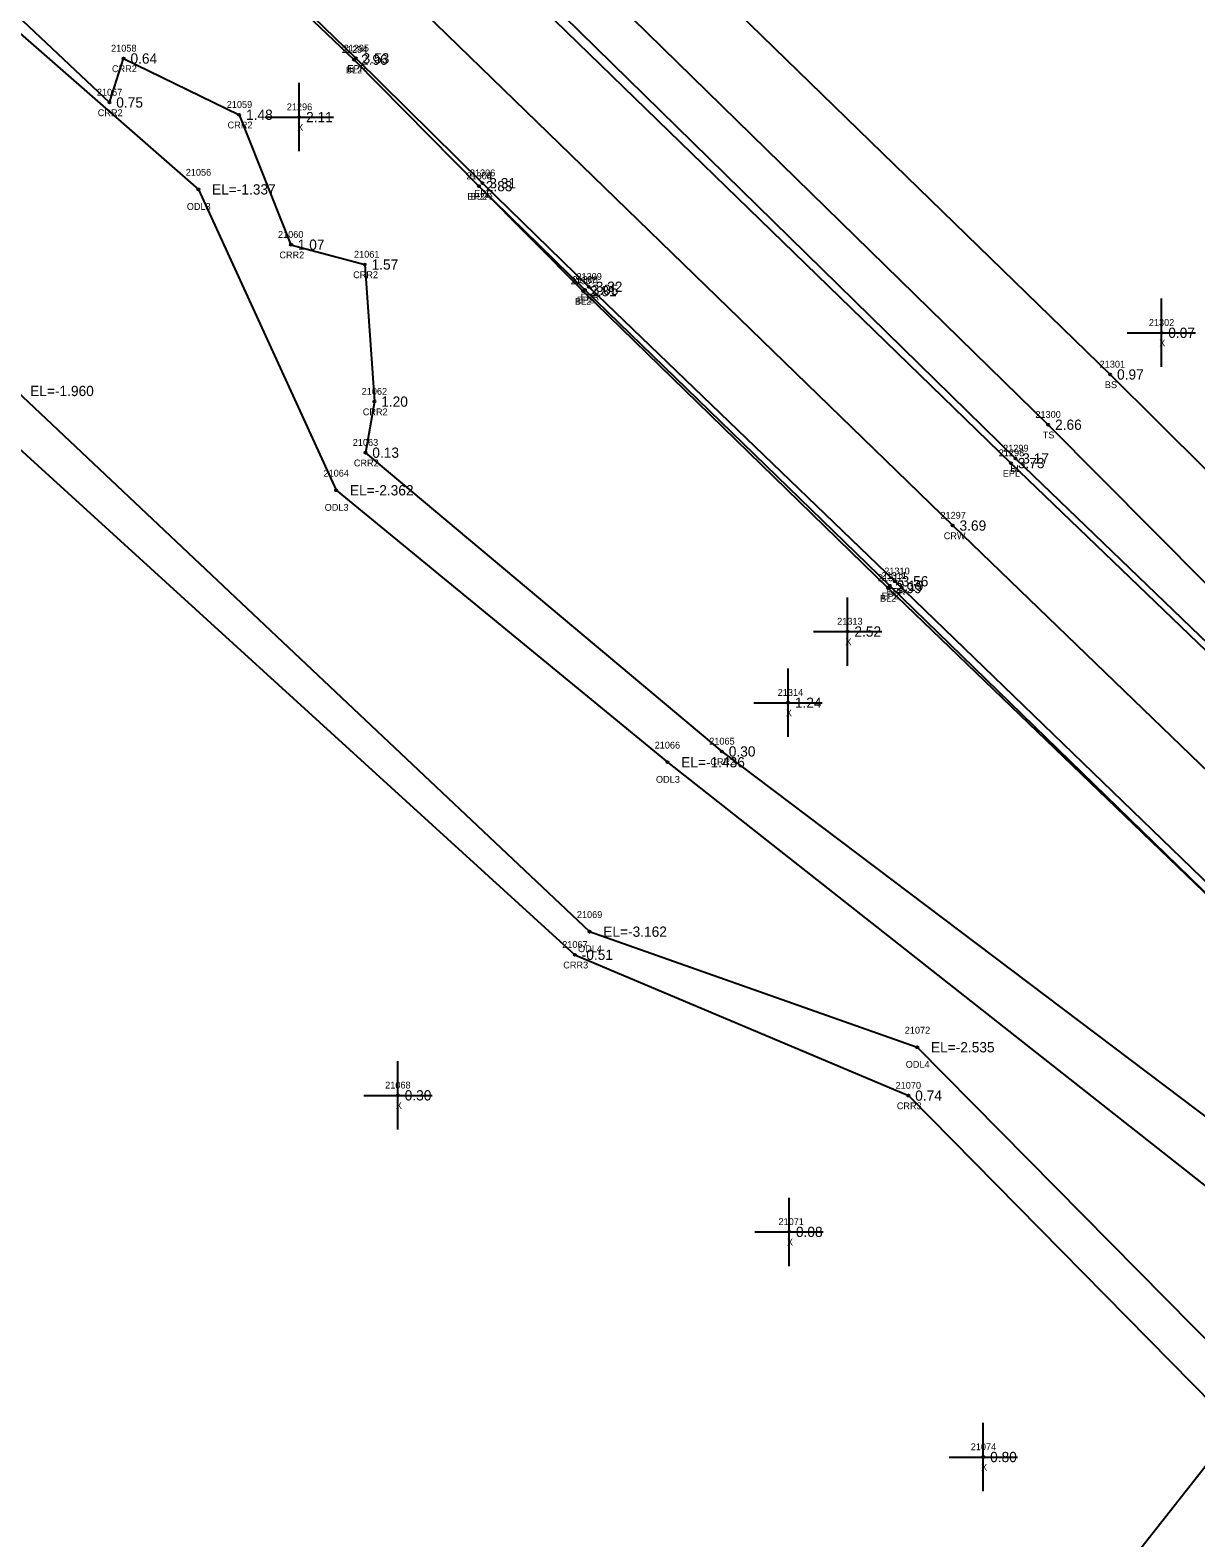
# Model space of a CAD drawing. Extents: x 2608745 to 2610333, y 641917 to 643463.
# Drawn here: x 2609715.3 to 2609885.8, y 642225.6 to 642446.2 of the extents above; entities that cross this region are included whole.
import ezdxf

# ---------------------------------------------------------------- set-up
doc = ezdxf.new("R2010")
doc.units = 0
for name, color, linetype in [('RD_DTM_BkLn1', 7, 'Continuous'), ('RD_DTM_BkLn2', 7, 'Continuous'), ('RD_DTM_BkLn_txCode', 7, 'Continuous'), ('RD_EX_H2O', 7, 'Continuous'), ('RD_EX_H2O_txCode', 7, 'Continuous'), ('RD_EX_Misc', 7, 'Continuous'), ('RD_EX_Misc_txCode', 7, 'Continuous'), ('RD_EX_Road', 7, 'Continuous'), ('RD_EX_Road_txCode', 7, 'Continuous'), ('RD_EX_TX_H2O_ELEV', 7, 'Continuous'), ('RD_EX_TX_Misc_ELEV', 7, 'Continuous'), ('RD_EX_TX_Road_ELEV', 7, 'Continuous'), ('RD_HC_Survey_ELEV', 7, 'Continuous'), ('RD_HC_Survey_txCode', 7, 'Continuous'), ('RD_SMD_Locator', 7, 'Continuous')]:
    doc.layers.add(name, color=color, linetype=linetype)

msp = doc.modelspace()

# ---------------------------------------------------------------- linework, layer by layer
at = {"layer": 'RD_DTM_BkLn1'}
for points in [[(2609568.4, 642647.43), (2609618.95, 642597.92), (2609693.89, 642525.38), (2609771.33, 642450.27), (2609850.26, 642373.69), (2609929.54, 642297.24), (2610000.01, 642230.49), (2610078.71, 642154.75), (2610156.09, 642080.44), (2610235.53, 642002.94), (2610263.59, 641975.77)], [(2609627.58, 642607.09), (2609630.23, 642605.37), (2609646.31, 642589.45), (2609703.16, 642535.02), (2609781.51, 642459.84), (2609859.44, 642383.51), (2609938.95, 642307.03), (2610008.76, 642239.49), (2610086.74, 642162.99), (2610105.31, 642145.89), (2610105.31, 642145.89), (2610140.26, 642113.1), (2610153.89, 642100.28), (2610164.72, 642089.82), (2610189.2, 642065.46)], [(2609638.64, 642561.68), (2609646.49, 642552.99), (2609655.41, 642544.68), (2609682.3, 642518.46), (2609696.97, 642504.35), (2609720.79, 642481.57), (2609738.97, 642465.02), (2609753.66, 642450.39), (2609762.69, 642441.83), (2609780.95, 642423.34), (2609796.2, 642407.99), (2609840.83, 642364.55), (2609897.27, 642310.29), (2609920.64, 642289.07), (2609961.88, 642250.25), (2609968.31, 642243.41), (2609978.92, 642233.98)]]:
    msp.add_lwpolyline(points, dxfattribs=at)
at = {"layer": 'RD_DTM_BkLn2'}
for points in [[(2609582.66, 642657.54), (2609585.75, 642657.34), (2609622.53, 642623.2), (2609632.13, 642611.9), (2609647.4, 642591.36), (2609682.93, 642558.52), (2609706.14, 642537.77), (2609755.54, 642496.98), (2609786.05, 642464.88), (2609864.24, 642388.44), (2609941.53, 642310.67), (2610012.94, 642244.46), (2610082.83, 642179.18), (2610093.52, 642170.29)], [(2609755.54, 642496.98), (2609777.06, 642487.55), (2609794.23, 642472.67), (2609873.31, 642395.79), (2609950.73, 642318.92), (2610015.83, 642247.73), (2610085.46, 642180.03), (2610093.52, 642170.29)]]:
    msp.add_lwpolyline(points, dxfattribs=at)
at = {"layer": 'RD_EX_H2O'}
for points in [[(2609550.15, 642638.19), (2609560.64, 642608.55), (2609596.58, 642544.67), (2609665.26, 642493.63), (2609726.89, 642435.57), (2609728.97, 642442.01), (2609745.88, 642433.78), (2609753.45, 642414.77), (2609764.24, 642411.87), (2609765.65, 642391.82), (2609764.35, 642384.35), (2609816.5, 642340.65), (2609898.67, 642278.63), (2609932.36, 642236.09), (2609918.8, 642192.33)], [(2609545.26, 642628.98), (2609557.91, 642602.6), (2609591.74, 642540.6), (2609658.48, 642494.06), (2609739.9, 642422.86), (2609760.07, 642378.85), (2609808.54, 642339.07), (2609896.37, 642269.89), (2609925.48, 642240.69), (2609915.11, 642188.91), (2609891.33, 642158.21), (2609835.84, 642063.03)], [(2609518.22, 642586.65), (2609536.97, 642578.99), (2609575.62, 642520.95), (2609643.94, 642461.12), (2609713.29, 642393.38), (2609797.14, 642314.29), (2609845.08, 642297.38), (2609901.61, 642240.2), (2609849.12, 642177.48), (2609793.89, 642090.6)], [(2609514.45, 642579.97), (2609534.32, 642569.3), (2609569.82, 642513.21), (2609640.11, 642458.03), (2609710.3, 642387.96), (2609794.99, 642310.91), (2609843.78, 642290.31), (2609891.67, 642241.7), (2609844.05, 642181.23), (2609787.66, 642090.39)]]:
    msp.add_lwpolyline(points, dxfattribs=at)
at = {"layer": 'RD_EX_Misc'}
for p, q in [((2609754.66, 642428.43), (2609754.66, 642438.43)), ((2609749.66, 642433.43), (2609759.66, 642433.43)), ((2609880.8, 642396.89), (2609880.8, 642406.89)), ((2609875.8, 642401.89), (2609885.8, 642401.89)), ((2609834.88, 642353.19), (2609834.88, 642363.19)), ((2609829.88, 642358.19), (2609839.88, 642358.19)), ((2609826.17, 642342.78), (2609826.17, 642352.78)), ((2609821.17, 642347.78), (2609831.17, 642347.78)), ((2609769.09, 642285.35), (2609769.09, 642295.35)), ((2609764.09, 642290.35), (2609774.09, 642290.35)), ((2609826.33, 642265.38), (2609826.33, 642275.38)), ((2609821.33, 642270.38), (2609831.33, 642270.38)), ((2609854.74, 642232.45), (2609854.74, 642242.45)), ((2609849.74, 642237.45), (2609859.74, 642237.45))]:
    msp.add_line(p, q, dxfattribs=at)
at = {"layer": 'RD_EX_Road'}
for points in [[(2609576.61, 642656.06), (2609590.88, 642642.24), (2609605.19, 642628.78), (2609627.58, 642607.09), (2609646.03, 642589.11), (2609702.18, 642534.04), (2609780.35, 642458.95), (2609858.79, 642382.83), (2609938.32, 642306.42), (2610008.62, 642239.32), (2610086.3, 642162.54), (2610164.18, 642089.49), (2610189.2, 642065.46), (2610214.78, 642040.19), (2610225.86, 642030.16), (2610226.32, 642028.39), (2610235.43, 642019.75), (2610260.23, 641995.63), (2610272.39, 641983.25)], [(2609560.29, 642639.04), (2609610.49, 642589.69), (2609620.39, 642580.29), (2609634.49, 642566.49), (2609647.6, 642554.19), (2609656.49, 642545.43), (2609683.33, 642519.48), (2609697.84, 642505.38), (2609722.29, 642481.47), (2609722.29, 642481.47), (2609722.29, 642481.47), (2609762.93, 642442.03), (2609781.47, 642423.77), (2609797.04, 642408.62), (2609841.8, 642365.54), (2609898.22, 642311.07)], [(2609780.95, 642423.34), (2609796.46, 642408.17), (2609841.07, 642364.89), (2609897.27, 642310.29)]]:
    msp.add_lwpolyline(points, dxfattribs=at)
at = {"layer": 'RD_SMD_Locator'}
for centre in [(2609728.97, 642442.01), (2609762.69, 642441.83), (2609762.93, 642442.03), (2609726.89, 642435.57), (2609745.88, 642433.78), (2609754.66, 642433.43), (2609780.95, 642423.34), (2609780.95, 642423.34), (2609781.47, 642423.77), (2609739.9, 642422.86), (2609753.45, 642414.77), (2609764.24, 642411.87), (2609796.2, 642407.99), (2609796.46, 642408.17), (2609797.04, 642408.62), (2609880.8, 642401.89), (2609873.31, 642395.79), (2609765.65, 642391.82), (2609864.24, 642388.44), (2609764.35, 642384.35), (2609859.44, 642383.51), (2609858.79, 642382.83), (2609760.07, 642378.85), (2609850.26, 642373.69), (2609840.83, 642364.55), (2609841.07, 642364.89), (2609841.8, 642365.54), (2609834.88, 642358.19), (2609826.17, 642347.78), (2609816.5, 642340.65), (2609808.54, 642339.07), (2609797.14, 642314.29), (2609794.99, 642310.91), (2609845.08, 642297.38), (2609769.09, 642290.35), (2609843.78, 642290.31), (2609826.33, 642270.38), (2609854.74, 642237.45)]:
    msp.add_circle(centre, 0.15, dxfattribs=at)

# ---------------------------------------------------------------- texts
at = {"layer": 'RD_DTM_BkLn_txCode'}
for s, p in [('21294', (2609760.9, 642442.83)), ('BL2', (2609761.49, 642439.83)), ('21304', (2609779.12, 642424.34)), ('BL2', (2609779.75, 642421.34)), ('21307', (2609794.37, 642408.99)), ('BL2', (2609795, 642405.99)), ('21301', (2609871.76, 642396.79)), ('BS', (2609872.53, 642393.79)), ('21300', (2609862.36, 642389.44)), ('TS', (2609863.44, 642386.44)), ('21299', (2609857.64, 642384.51)), ('BL', (2609858.68, 642381.51)), ('21312', (2609839.32, 642365.55)), ('BL2', (2609839.63, 642362.55))]:
    msp.add_text(s, height=1, dxfattribs=at).set_placement(p)
at = {"layer": 'RD_EX_H2O_txCode'}
for s, p in [('21058', (2609727.13, 642443.01)), ('CRR2', (2609727.26, 642440.01)), ('21057', (2609725.05, 642436.57)), ('CRR2', (2609725.18, 642433.57)), ('21059', (2609744.05, 642434.78)), ('CRR2', (2609744.18, 642431.78)), ('21056', (2609738.05, 642424.86)), ('ODL3', (2609738.21, 642419.86)), ('21060', (2609751.55, 642415.77)), ('CRR2', (2609751.75, 642412.77)), ('21061', (2609762.67, 642412.87)), ('CRR2', (2609762.54, 642409.87)), ('21062', (2609763.79, 642392.82)), ('CRR2', (2609763.95, 642389.82)), ('21063', (2609762.49, 642385.35)), ('21064', (2609758.21, 642380.85)), ('CRR2', (2609762.65, 642382.35)), ('ODL3', (2609758.38, 642375.85)), ('21066', (2609806.66, 642341.07)), ('21065', (2609814.64, 642341.65)), ('CRR2', (2609814.8, 642338.65)), ('ODL3', (2609806.85, 642336.07)), ('21069', (2609795.28, 642316.29)), ('21067', (2609793.13, 642311.91)), ('ODL4', (2609795.45, 642311.29)), ('CRR3', (2609793.29, 642308.91)), ('21072', (2609843.25, 642299.38)), ('ODL4', (2609843.39, 642294.38)), ('21070', (2609841.91, 642291.31)), ('CRR3', (2609842.08, 642288.31))]:
    msp.add_text(s, height=1, dxfattribs=at).set_placement(p)
at = {"layer": 'RD_EX_Misc_txCode'}
for s, p in [('21296', (2609752.84, 642434.43)), ('X', (2609754.35, 642431.43)), ('21302', (2609878.96, 642402.89)), ('X', (2609880.48, 642399.89)), ('21313', (2609833.36, 642359.19)), ('X', (2609834.56, 642356.19)), ('21314', (2609824.66, 642348.78)), ('X', (2609825.85, 642345.78)), ('21068', (2609767.23, 642291.35)), ('X', (2609768.78, 642288.35)), ('21071', (2609824.78, 642271.38)), ('X', (2609826.01, 642268.38)), ('21074', (2609852.9, 642238.45)), ('X', (2609854.42, 642235.45))]:
    msp.add_text(s, height=1, dxfattribs=at).set_placement(p)
at = {"layer": 'RD_EX_Road_txCode'}
for s, p in [('21295', (2609761.14, 642443.03)), ('EPR', (2609761.7, 642440.03)), ('21306', (2609779.62, 642424.77)), ('21305', (2609779.12, 642424.34)), ('EP2A', (2609779.26, 642421.34)), ('EPR', (2609780.25, 642421.77)), ('21308', (2609794.63, 642409.17)), ('21309', (2609795.21, 642409.62)), ('EP2', (2609795.26, 642406.17)), ('EPR', (2609795.82, 642406.62)), ('21298', (2609857, 642383.83)), ('EPL', (2609857.59, 642380.83)), ('21311', (2609839.84, 642365.89)), ('21310', (2609840.25, 642366.54)), ('EP2', (2609839.86, 642362.89)), ('EPR', (2609840.57, 642363.54))]:
    msp.add_text(s, height=1, dxfattribs=at).set_placement(p)
at = {"layer": 'RD_EX_TX_H2O_ELEV'}
for s, p in [('0.64', (2609729.97, 642441.26)), ('0.75', (2609727.89, 642434.82)), ('1.48', (2609746.88, 642433.03)), ('EL=-1.337', (2609741.9, 642422.11)), ('1.07', (2609754.45, 642414.02)), ('1.57', (2609765.24, 642411.12)), ('EL=-1.960', (2609715.29, 642392.63)), ('1.20', (2609766.65, 642391.07)), ('0.13', (2609765.35, 642383.6)), ('EL=-2.362', (2609762.07, 642378.1)), ('EL=-1.436', (2609810.54, 642338.32)), ('0.30', (2609817.5, 642339.9)), ('EL=-3.162', (2609799.14, 642313.54)), ('-0.51', (2609795.99, 642310.16)), ('EL=-2.535', (2609847.08, 642296.63)), ('0.74', (2609844.78, 642289.56))]:
    msp.add_text(s, height=1.5, dxfattribs=at).set_placement(p)
at = {"layer": 'RD_EX_TX_Misc_ELEV'}
for s, p in [('2.96', (2609763.69, 642441.08)), ('2.11', (2609755.66, 642432.68)), ('2.83', (2609781.95, 642422.59)), ('2.81', (2609797.2, 642407.24)), ('0.07', (2609881.8, 642401.14)), ('0.97', (2609874.31, 642395.04)), ('2.66', (2609865.24, 642387.69)), ('3.17', (2609860.44, 642382.76)), ('2.99', (2609841.83, 642363.8)), ('2.52', (2609835.88, 642357.44)), ('1.24', (2609827.17, 642347.03)), ('0.30', (2609770.09, 642289.6)), ('0.08', (2609827.33, 642269.63)), ('0.80', (2609855.74, 642236.7))]:
    msp.add_text(s, height=1.5, dxfattribs=at).set_placement(p)
at = {"layer": 'RD_EX_TX_Road_ELEV'}
for s, p in [('3.53', (2609763.93, 642441.28)), ('2.83', (2609781.95, 642422.59)), ('3.31', (2609782.47, 642423.02)), ('3.05', (2609797.46, 642407.42)), ('3.32', (2609798.04, 642407.87)), ('3.73', (2609859.79, 642382.08)), ('3.56', (2609842.8, 642364.79)), ('3.19', (2609842.07, 642364.14))]:
    msp.add_text(s, height=1.5, dxfattribs=at).set_placement(p)
at = {"layer": 'RD_HC_Survey_ELEV'}
msp.add_text('3.69', height=1.5, dxfattribs=at).set_placement((2609851.26, 642372.94))
at = {"layer": 'RD_HC_Survey_txCode'}
for s, p in [('21297', (2609848.47, 642374.69)), ('CRW', (2609848.95, 642371.69))]:
    msp.add_text(s, height=1, dxfattribs=at).set_placement(p)

doc.saveas('drawing.dxf')
